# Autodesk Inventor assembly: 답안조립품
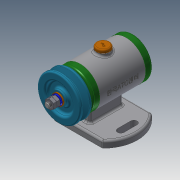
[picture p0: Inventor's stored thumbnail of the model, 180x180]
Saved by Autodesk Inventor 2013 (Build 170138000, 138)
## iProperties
Created: 2021-09
Part Number: 답안조립품
Document SubType Name: Assembly
Designer: user
Author: user
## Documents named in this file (14)
- C:\Users\user\Desktop\710906V1028\답안조립품.iam
- C:\Users\user\Desktop\710906V1028\본체.ipt
- C:\Users\user\Desktop\710906V1028\V벨트풀리.ipt
- C:\Users\user\Desktop\710906V1028\너트 M8.ipt
- C:\Users\user\Desktop\710906V1028\뒤커버.ipt
- C:\Users\user\Desktop\710906V1028\베어링 15x32x9.ipt
- C:\Users\user\Desktop\710906V1028\볼트 M4x12.ipt
- C:\Users\user\Desktop\710906V1028\스프링와셔 8.ipt
- C:\Users\user\Desktop\710906V1028\앞커버.ipt
- C:\Users\user\Desktop\710906V1028\오일 실 15x25x7.ipt
- C:\Users\user\Desktop\710906V1028\와셔 8x17.ipt
- C:\Users\user\Desktop\710906V1028\축.ipt
- C:\Users\user\Desktop\710906V1028\캡.ipt
- C:\Users\user\Desktop\710906V1028\키 3x3.ipt
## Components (1 placed, 1 different names)
1. V벨트풀리:1
